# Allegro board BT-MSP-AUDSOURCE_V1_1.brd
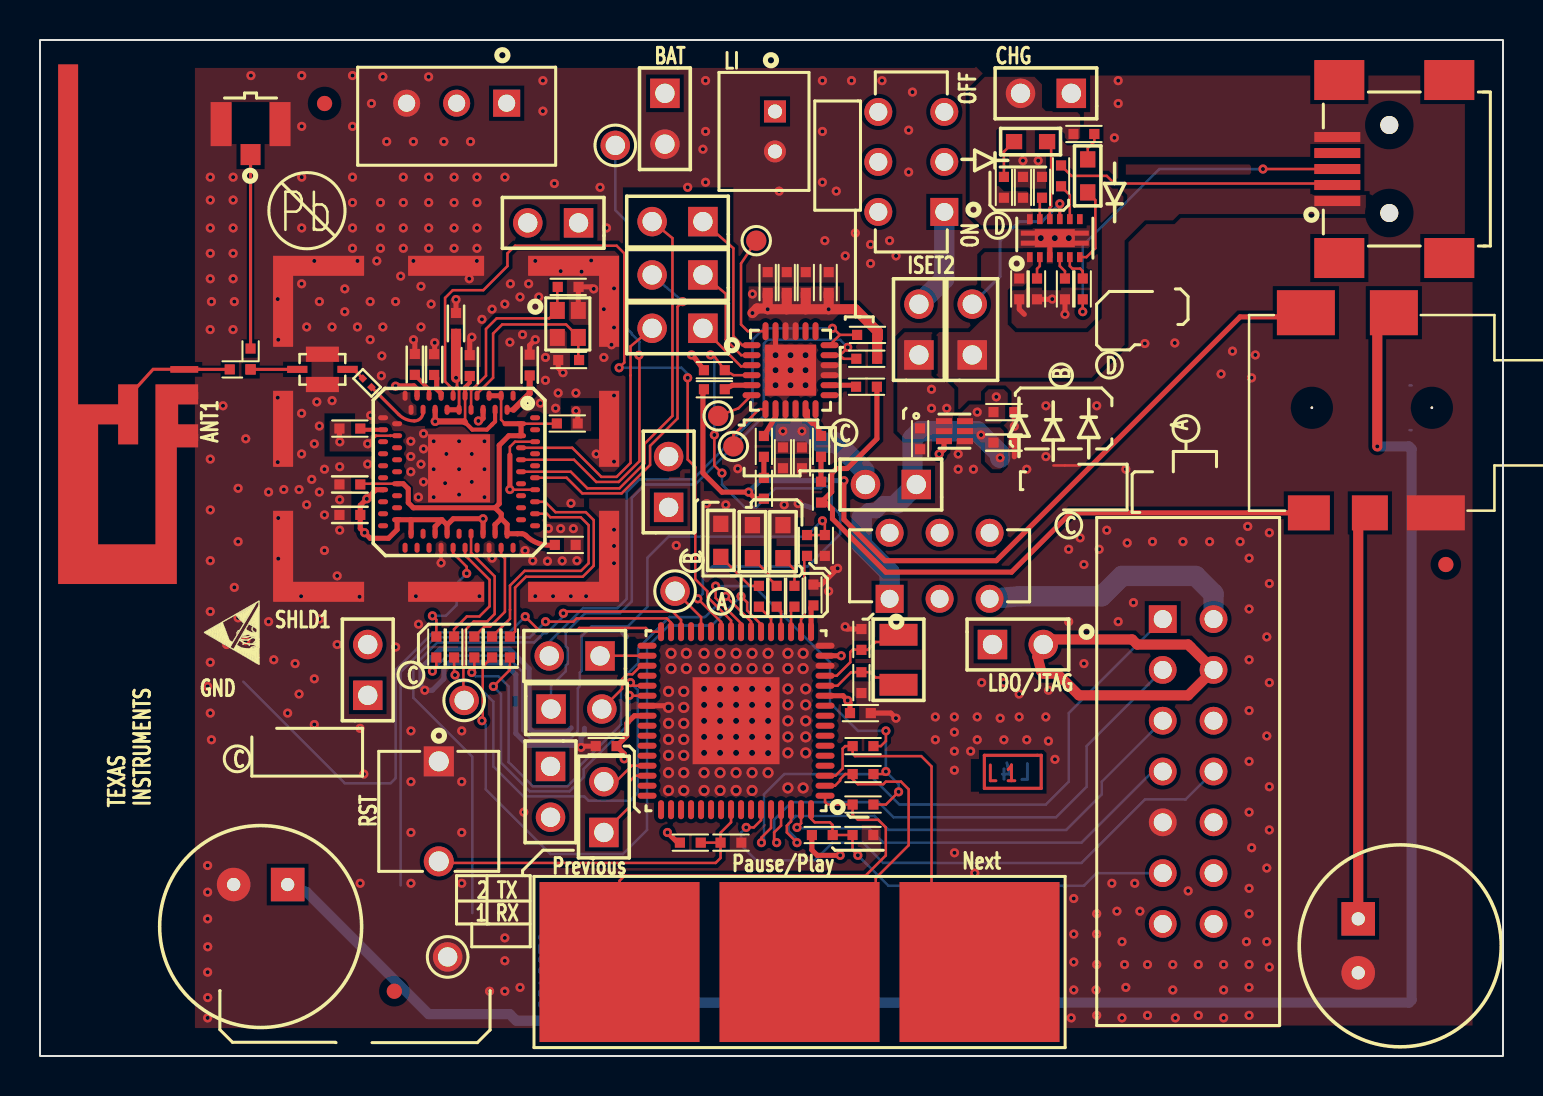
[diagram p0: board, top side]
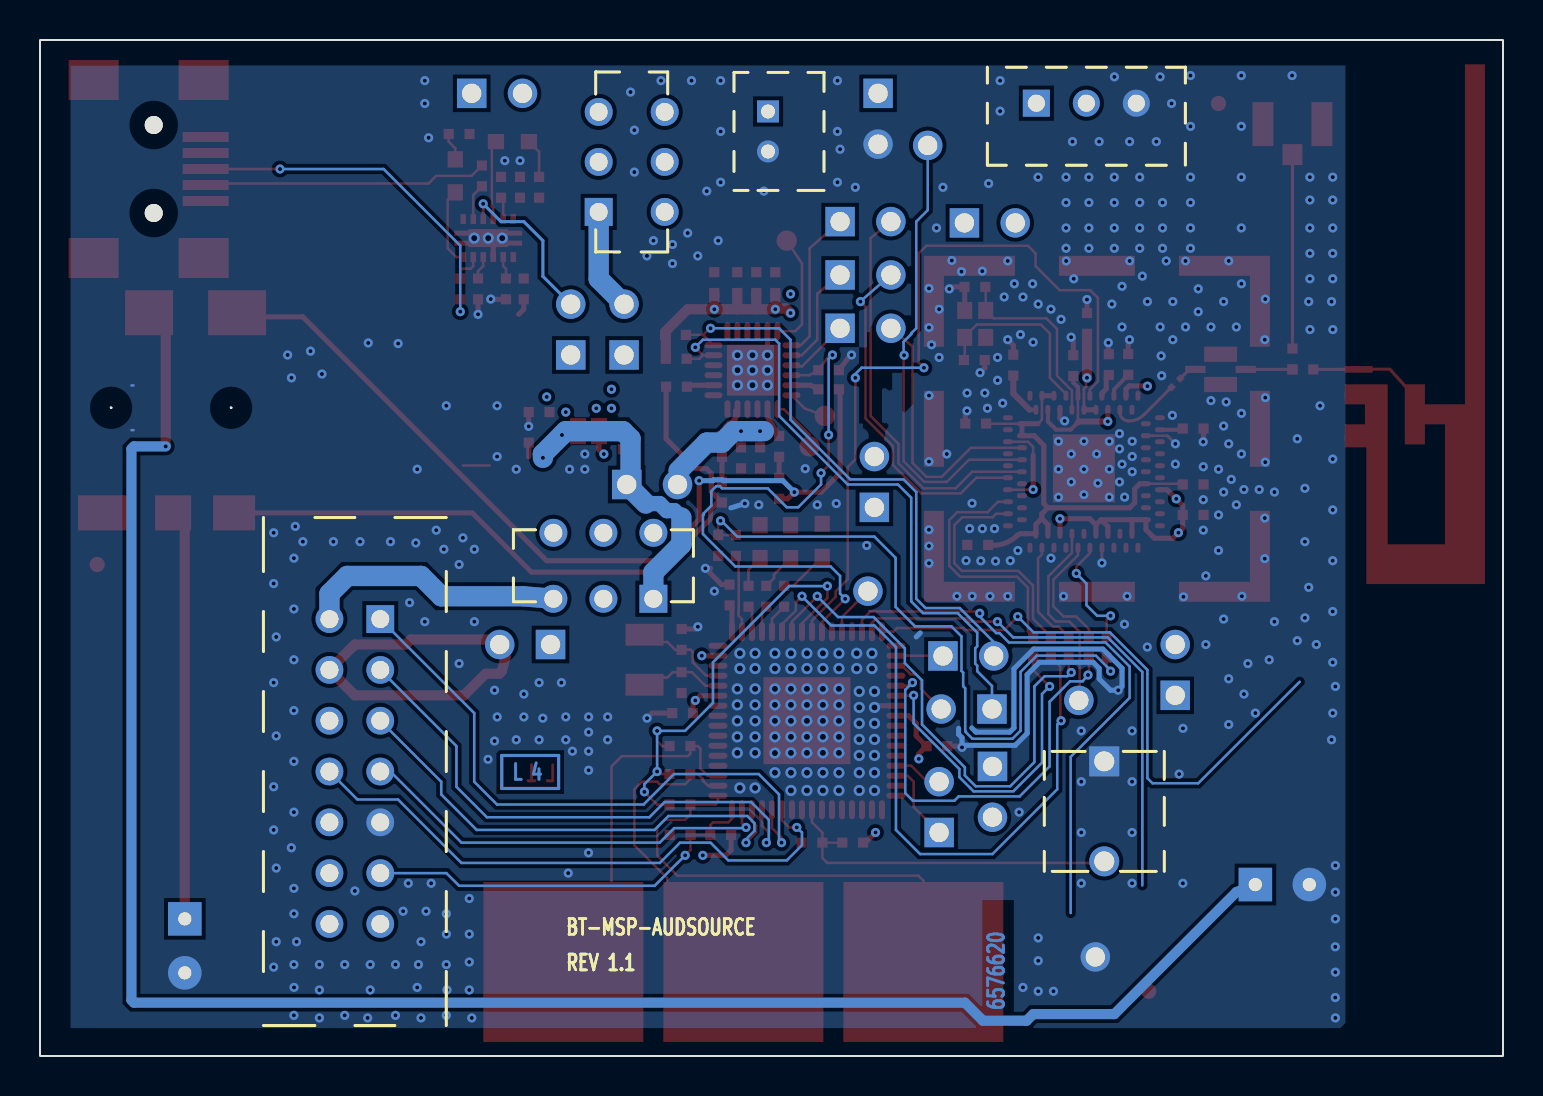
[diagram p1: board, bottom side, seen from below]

Outline 73.15 x 50.8 mm; copper layers: TOP, LYR2_GND, LYR3_PWR, BOTTOM. Coordinates in mm from the lower left corner of the outline.
Outline path: rectangle 0,0 73.15,50.8

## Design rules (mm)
net group PWR: nets DIG_LDO_OUT JTAG_PWR_3V3 VBAT_CC VCORE
nets with their own width: min track width 0.076; nets MLDO_OUT

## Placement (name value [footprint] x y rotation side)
ANT1  2.4-2.5 GHz  [ANT_IIFA_CC2420_32MIL_MIR_1]  7.21 37.73 90 top
C17  0.1uF  [0402]  15.49 27.05 180 top
C20  1.0uF  [0402]  21.49 34.52 90 top
C21  1.0uF  [0402]  20.8 36.63 90 top
C22  12pF  [0402]  26.41 38.46 180 top
C23  12pF  [0402]  26.43 34.8 0 top
C24  1.0uF  [0402]  48.2 30.67 0 top
C25  0.47uF  [0402]  15.49 28.58 180 top
C26  0.47uF  [0402]  26.26 25.56 0 top
C27  0.1uF  [0402]  15.49 31.37 180 top
C28  0.1uF  [0402]  19.71 34.57 90 top
C29  0.1uF  [0402]  18.74 34.58 90 top
C30  0.1uF  [0402]  24.48 34.55 90 top
C31  22pF  [0201]  16.36 33.66 135 top
C32  1.0uF  [0402]  48.96 38.35 270 top
C33  1.0uF  [0402]  48.2 32.19 0 top
C35  0.1uF  [0402]  26.36 31.63 0 top
C36  1.0uF  [0402]  49.15 43.43 90 top
C37  10uF  [0402]  28.31 15.49 180 top
C39  1.0uF  [0402]  41.02 17.14 0 top
C41  470nF  [0402]  38.67 23.05 90 top
C43  2.2nF  [0402]  41.15 11.05 0 top
C44  2.2nF  [0402]  34.55 10.67 0 top
C45  1.0uF  [0402]  44.01 30.86 270 top
C46  12pF  [0402]  41.07 20.83 270 top
C47  12pF  [0402]  41.07 18.67 90 top
C51  0.1uF  [0402]  38.1 29.91 90 top
C52  1.0uF  [0402]  37.15 29.91 90 top
C53  0.1uF  [0402]  37.34 38.67 90 top
C54  1.0uF  [0402]  36.39 38.67 90 top
C55  0.1uF  [0402]  38.29 38.67 90 top
C56  1.0uF  [0402]  39.43 38.67 90 top
C60  0.47uF  [0402]  39.05 30.48 90 top
C61  0.47uF  [0402]  36.2 30.48 90 top
D1  ORN  [LED_0603]  49.53 45.72 0 top
D2  YLW  [LED_0603]  37.15 25.72 90 top
D3  RED  [LED_0603]  35.62 25.72 90 top
D4  GRN  [LED_0603]  52.39 44.01 270 top
D5  GRN  [LED_0603]  34.04 25.78 90 top
FL1  2.45GHz  [FIL_4_85X53X41]  14.12 34.33 180 top
J2  MSP430 JTAG  [TE_5103308-2]  56.14 21.84 270 top
J3  LI-POL BAT HEADER  [JST_B2B-PH-K-S]  36.75 47.23 270 top
J4  USB Port  [JAE_DX2R005HN2]  69.32 44.35 90 top
J5  1x2 THVT  [HDR_THVT_1X2_100_M]  25.53 14.48 0 top
J6  1x2 THVT  [HDR_THVT_1X2_100_M]  47.62 20.57 90 top
J11  1x2 THVT  [HDR_THVT_1X2_100_M]  26.93 41.66 270 top
J12  1x2 THVT  [HDR_THVT_1X2_100_M]  16.39 18.03 180 top
J13  1x2 THVT  [HDR_THVT_1X2_100_M]  51.57 48.13 270 top
J14  1x2 THVT  [HDR_THVT_1X2_100_M]  46.61 35.05 180 top
J15  1x2 THVT  [HDR_THVT_1X2_100_M]  28.19 11.18 180 top
J16  1x2 THVT  [HDR_THVT_1X2_100_M]  43.95 35.05 180 top
J17  HEADER 1  [TP101H50]  31.76 23.24 270 top
J18  HEADER 1  [TP101H50]  21.21 17.78 0 top
J22  1x2 THVT  [HDR_THVT_1X2_100_M]  31.25 48.13 0 top
J23  HEADER 1  [TP101H50]  28.77 45.53 0 top
J26  AA BAT HEADER  [MOLEX_22-03-5035]  23.33 47.64 180 top
J28  MIC1  [MIC_THVT_CMA-4544PF-W]  12.38 8.57 180 top
J29  HEADER 1  [TP101H50]  20.38 4.95 0 top
J30  1x2 THVT  [HDR_THVT_1X2_100_M]  43.81 28.57 270 top
J31  1x2 THVT  [HDR_THVT_1X2_100_M]  31.43 27.43 180 top
J32  1x2 THVT  [HDR_THVT_1X2_100_M]  33.15 41.72 270 top
J33  1x2 THVT  [HDR_THVT_1X2_100_M]  33.15 39.05 270 top
J34  1x2 THVT  [HDR_THVT_1X2_100_M]  25.55 17.35 90 top
J35  1x2 THVT  [HDR_THVT_1X2_100_M]  33.15 36.39 270 top
J36  1x2 THVT  [HDR_THVT_1X2_100_M]  28 20 270 top
J37  MIC2  [MIC_THVT_CMA-4544PF-W]  65.91 6.86 270 top
J39  PHONOJACK STEREO-15  [JACK_SM_SJ1_3515]  69.6 32.41 180 top
NOREF  -  []  5.96 81.94 90 top
NOREF#2  -  [unnamed#2]  14.23 47.62 0 top
NOREF#3  -  [unnamed#2]  70.29 24.57 0 top
NOREF#4  -  []  363.1 -64.01 0 top
NOREF#5  -  []  25.53 15.62 90 top
NOREF#6  -  []  24.52 16.64 180 top
NOREF#7  -  []  18.55 38.86 180 top
NOREF#8  -  []  25.53 38.86 180 top
NOREF#9  -  []  13.09 16.64 90 top
NOREF#10  -  []  18.55 38.86 180 top
NOREF#11  -  []  25.53 15.62 180 top
NOREF#12  -  [unnamed#2]  17.72 3.24 0 top
NOREF#13  -  []  17.28 38.86 180 top
NOREF#14  -  []  38.74 61.01 180 bottom
P3  COAXIAL  [HRS_U-FL-R-SMT-1]  10.53 46.6 0 top
R3  2.7K  [0402]  49.85 38.35 270 top
R4  1.5K  [0402]  48.2 43.43 90 top
R5  2.0K  [0402]  51.25 38.35 270 top
R6  470R  [0402]  37.72 22.99 90 top
R7  470R  [0402]  36.84 22.99 90 top
R8  10K  [0402]  50.1 43.43 90 top
R9  1.5K  [0402]  52.2 46.1 0 top
R10  10K  [0402]  38.35 25.53 90 top
R11  18K  [0402]  39.24 25.53 270 top
R12  47K  [0402]  32.52 10.67 0 top
R13  0R  [0402]  51.05 44.01 270 top
R14  0R  [0402]  52.14 38.35 90 top
R15  470R  [0402]  35.95 22.99 90 top
R16  2.7K  [0402]  41.34 34.86 180 top
R17  2.7K  [0402]  41.38 36.06 180 top
R19  2.2K  [0402]  33.72 33.34 0 top
R20  2.2K  [0402]  41.33 33.46 0 top
R25  0R  [0402]  19.82 20.45 270 top
R26  0R  [0402]  23.5 20.45 270 top
R27  0R  [0402]  20.71 20.45 270 top
R28  47K  [0402]  39.12 11.05 0 top
R29  0R  [0402]  10.01 34.33 0 top
R30  0R  [0402]  10.53 34.85 270 top
R31  75k  [0402]  41.15 12.57 180 top
R32  75k  [0402]  41.15 14.1 180 top
R33  75k  [0402]  41.15 15.49 180 top
R34  0R  [0402]  22.61 20.45 270 top
R35  0R  [0402]  21.72 20.45 270 top
R36  0R  [0402]  36.2 28.38 270 top
R37  0R  [0402]  39.05 28.19 270 top
R39  10K  [0402]  33.72 34.29 180 top
S1  BUTTON  [SW_EVQ-11A05R]  19.94 14.73 270 top
S2  POS 2 SW  [SW_JS202011CQN]  45.22 42.2 180 top
S3  POS 2 SW  [SW_JS202011CQN]  42.48 22.86 90 top
SHLD1  RF SHIELD COVER  [SH_BMI-S-202_650X650]  28.96 22.71 90 top
TP7  XX  [TP102]  35.81 40.77 0 top
TP8  XX  [TP102]  34.67 30.48 0 top
TP11  XX  [TP102]  33.91 32 0 top
U5  CC2560RVM  [PVQFN_RVM_EP134X122]  20.95 29.21 180 top
U8  TLV7101828DSER  [SON50P150X150X80-6]  45.73 31.24 270 top
U9  BQ24055DSST  [SON50P300X200X80-13]  50.74 40.89 90 top
U10  MSP430F5229IRGCR  [QFN50P900X900X100-65NA]  34.8 16.76 180 top
U11  Electrodes  [3PELECTRODE]  37.98 4.7 0 top
U12  TLV320ADC3101  [QFN50P400X400X100-25N]  37.53 34.29 0 top
Y1  26MHz  [XTAL200X160X50]  26.39 36.6 0 top
Y2  32.768KHz  [XTAL_2_SM_130X63]  42.93 19.81 90 top

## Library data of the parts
ANT1 = ANT_IIFA_CC2420_32mil_MIR
C17 C20-C30 C32 C33 C35-C37 C39 C41 C43-C47 C51-C56 C60 C61 = CAP_NP: alternate symbols: (0402_SMALL)
C31 = CAP_NP: alternate symbols: (0201_small)
D1-D5 = LED_2P
FL1 = FILTER_4PIN_GND
J2 = CONN PCB 7x2
J3 = BATTERY
J4 = USB Port_3
J5 J6 J11-J16 J22 J30-J36 = Header_1x2
J17 J18 J23 J29 = HEADER 1
J26 = AA BAT HEADER
J28 J37 = MIC_0
J39 = PHONOJACK STEREO-15
P3 = CON_COAXIAL_UFL-R-SMT_0
R3-R17 R19 R20 R25-R37 R39 = RESISTOR: alternate symbols: (0402_SMALL)
S1 = BUTTON
S2 = BUTTON_3
S3 = Switch_0
SHLD1 = RF_SHIELD_8P
TP7 TP8 TP11 = TESTPOINT
U5 = BL6450Q_RVM
U8 = TLV7101828_0
U9 = bq24055_1
U10 = MSP430F5229IRGC_1
U11 = Electrodes
U12 = TLV320ADC3101_0
Y1 = XTAL_4P_GND
Y2 = 32_12.768KHz

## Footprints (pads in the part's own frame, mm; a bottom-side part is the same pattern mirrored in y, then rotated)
3PELECTRODE
  rect 8x8 smd: 1(-9,0) 2(0,0) 3(9,0)
0201
  rect 0.305x0.305 smd: 1(-0.305,0) 2(0.305,0)
0402
  rect 0.508x0.508 smd: 1(-0.521,0) 2(0.521,0)
ANT_IIFA_CC2420_32MIL_MIR_1
  rect 0.33x1.397 smd: 1(-3.404,0) 2(-4.699,0) 3(-6.807,0)
FIL_4_85X53X41
  rect 1.651x0.762 smd: 1(0,0.757) 3(0,-0.757)
  rect 1.016x0.356 smd: 2(1.257,0) 4(-1.257,0)
HDR_THVT_1X2_100_M
  rect 1.473x1.473 hole 0.965: 1(0,0)
  round 1.473 hole 0.965: 2(0,-2.54)
HRS_U-FL-R-SMT-1
  rect 1x1.05 smd: 1(0,-1.525)
  rect 1.05x2.2 smd: 2A(-1.475,0) 2B(1.475,0)
JACK_SM_SJ1_3515
  round 0.127 hole 1.6 unplated: (0,0) (6,0)
  rect 2.9x1.75 smd: 1(-0.2,5.254)
  rect 2.9x2.25 smd: 2(6.3,-4.754)
  rect 2.1x1.75 smd: 3(6.15,5.254)
  rect 2.4x2.25 smd: 4(1.9,-4.754)
  rect 1.8x1.75 smd: 5(3.1,5.254)
JAE_DX2R005HN2
  round 0.9 hole 0.899 unplated: (-2.2,1.85) (2.2,1.85)
  rect 0.5x2.3 smd: 1(-1.6,4.45) 2(-0.8,4.45) 3(0,4.45) 4(0.8,4.45) 5(1.6,4.45)
  rect 2x2.5 smd: G1(-4.45,4.35) G2(4.45,4.35) G3(-4.45,-1.15) G4(4.45,-1.15)
JST_B2B-PH-K-S
  rect 1.1x1.1 hole 0.7: 1(0,0)
  round 1.1 hole 0.7: 2(2,0)
LED_0603
  rect 0.813x0.762 smd: 1(-0.826,0) 2(0.826,0)
MIC_THVT_CMA-4544PF-W
  rect 1.676x1.676 hole 0.66: 1(0,0)
  round 1.676 hole 0.66: 2(2.7,0)
MOLEX_22-03-5035
  rect 1.354x1.354 hole 0.854: 1(0,0)
  round 1.354 hole 0.854: 2(2.5,0) 3(5,0)
PVQFN_RVM_EP134X122
  oval 0.25x0.5 smd: A1(-2.7,-3.8) A2(-2.101,-3.8) A3(-1.501,-3.8) A4(-0.899,-3.8) A5(-0.3,-3.8) A6(0.3,-3.8) A7(0.899,-3.8) A8(1.501,-3.8) A9(2.101,-3.8) A10(2.7,-3.8) A21(2.7,3.8) A22(2.101,3.8) A23(1.501,3.8) A24(0.899,3.8) A25(0.3,3.8) A26(-0.3,3.8) A27(-0.899,3.8) A28(-1.501,3.8) A29(-2.101,3.8) A30(-2.7,3.8) B1(-2.4,-3.099) B2(-1.801,-3.099) B3(-1.199,-3.099) B4(-0.599,-3.099) B5(0,-3.099) B6(0.599,-3.099) B7(1.199,-3.099) B8(1.801,-3.099) B9(2.4,-3.099) B19(2.4,3.099) B20(1.801,3.099) B21(1.199,3.099) B22(0.599,3.099) B23(0,3.099) B24(-0.599,3.099) B25(-1.199,3.099) B26(-1.801,3.099) B27(-2.4,3.099)
  oval 0.5x0.25 smd: A11(3.8,-2.7) A12(3.8,-2.101) A13(3.8,-1.501) A14(3.8,-0.899) A15(3.8,-0.3) A16(3.8,0.3) A17(3.8,0.899) A18(3.8,1.501) A19(3.8,2.101) A20(3.8,2.7) A31(-3.8,2.7) A32(-3.8,2.101) A33(-3.8,1.501) A34(-3.8,0.899) A35(-3.8,0.3) A36(-3.8,-0.3) A37(-3.8,-0.899) A38(-3.8,-1.501) A39(-3.8,-2.101) A40(-3.8,-2.7) B10(3.099,-2.4) B11(3.099,-1.801) B12(3.099,-1.199) B13(3.099,-0.599) B14(3.099,0) B15(3.099,0.599) B16(3.099,1.199) B17(3.099,1.801) B18(3.099,2.4) B28(-3.099,2.4) B29(-3.099,1.801) B30(-3.099,1.199) B31(-3.099,0.599) B32(-3.099,0) B33(-3.099,-0.599) B34(-3.099,-1.199) B35(-3.099,-1.801) B36(-3.099,-2.4)
  rect 3.099x3.404 smd: EPAD(0,-0.17)
QFN50P400X400X100-25N
  oval 0.9x0.3 smd: 1(-1.95,1.25) 2(-1.95,0.75) 3(-1.95,0.25) 4(-1.95,-0.25) 5(-1.95,-0.75) 6(-1.95,-1.25) 13(1.95,-1.25) 14(1.95,-0.75) 15(1.95,-0.25) 16(1.95,0.25) 17(1.95,0.75) 18(1.95,1.25)
  oval 0.3x0.9 smd: 7(-1.25,-1.95) 8(-0.75,-1.95) 9(-0.25,-1.95) 10(0.25,-1.95) 11(0.75,-1.95) 12(1.25,-1.95) 19(1.25,1.95) 20(0.75,1.95) 21(0.25,1.95) 22(-0.25,1.95) 23(-0.75,1.95) 24(-1.25,1.95)
  rect 2.55x2.55 smd: 25(0,0)
QFN50P900X900X100-65NA
  oval 0.95x0.3 smd: 1(-4.45,3.75) 2(-4.45,3.25) 3(-4.45,2.75) 4(-4.45,2.25) 5(-4.45,1.75) 6(-4.45,1.25) 7(-4.45,0.75) 8(-4.45,0.25) 9(-4.45,-0.25) 10(-4.45,-0.75) 11(-4.45,-1.25) 12(-4.45,-1.75) 13(-4.45,-2.25) 14(-4.45,-2.75) 15(-4.45,-3.25) 16(-4.45,-3.75) 33(4.45,-3.75) 34(4.45,-3.25) 35(4.45,-2.75) 36(4.45,-2.25) 37(4.45,-1.75) 38(4.45,-1.25) 39(4.45,-0.75) 40(4.45,-0.25) 41(4.45,0.25) 42(4.45,0.75) 43(4.45,1.25) 44(4.45,1.75) 45(4.45,2.25) 46(4.45,2.75) 47(4.45,3.25) 48(4.45,3.75)
  oval 0.3x0.95 smd: 17(-3.75,-4.45) 18(-3.25,-4.45) 19(-2.75,-4.45) 20(-2.25,-4.45) 21(-1.75,-4.45) 22(-1.25,-4.45) 23(-0.75,-4.45) 24(-0.25,-4.45) 25(0.25,-4.45) 26(0.75,-4.45) 27(1.25,-4.45) 28(1.75,-4.45) 29(2.25,-4.45) 30(2.75,-4.45) 31(3.25,-4.45) 32(3.75,-4.45) 49(3.75,4.45) 50(3.25,4.45) 51(2.75,4.45) 52(2.25,4.45) 53(1.75,4.45) 54(1.25,4.45) 55(0.75,4.45) 56(0.25,4.45) 57(-0.25,4.45) 58(-0.75,4.45) 59(-1.25,4.45) 60(-1.75,4.45) 61(-2.25,4.45) 62(-2.75,4.45) 63(-3.25,4.45) 64(-3.75,4.45)
  rect 4.35x4.35 smd: 65(0,0)
SH_BMI-S-202_650X650
  rect 0.356x0.356 smd: 1(0.5,0.5) 2(8.65,0.5) 3(16.75,0.5) 4(16.8,8.65) 5(16.75,16.75) 6(8.65,16.8) 7(0.5,16.75) 8(0.5,8.65)
SON50P150X150X80-6
  rect 0.3x0.8 smd: 1(-0.5,-0.525) 2(0,-0.525) 3(0.5,-0.525) 4(0.5,0.525) 5(0,0.525) 6(-0.5,0.525)
SON50P300X200X80-13
  rect 0.5x0.28 smd: 1(-0.95,1.25) 2(-0.95,0.75) 3(-0.95,0.25) 4(-0.95,-0.25) 5(-0.95,-0.75) 6(-0.95,-1.25) 7(0.95,-1.25) 8(0.95,-0.75) 9(0.95,-0.25) 10(0.95,0.25) 11(0.95,0.75) 12(0.95,1.25)
  custom 0.225x0.225 smd: 13(0,0)
SW_EVQ-11A05R
  rect 1.5x1.5 hole 1: 1(0,0)
  round 1.5 hole 1: 2(5,0)
SW_JS202011CQN
  rect 1.4x1.4 hole 0.899: 1(0,0)
  round 1.4 hole 0.899: 2(0,-2.5) 3(0,-5) 4(3.3,0) 5(3.3,-2.5) 6(3.3,-5)
TE_5103308-2
  rect 1.39x1.39 hole 0.899: 1(0,0)
  round 1.39 hole 0.899: 2(0,2.54) 3(2.54,0) 4(2.54,2.54) 5(5.08,0) 6(5.08,2.54) 7(7.62,0) 8(7.62,2.54) 9(10.16,0) 10(10.16,2.54) 11(12.7,0) 12(12.7,2.54) 13(15.24,0) 14(15.24,2.54)
TP101H50
  round 1.473 hole 0.965: 1(0,0)
TP102
  round 1.016 smd: 1(0,0)
unnamed#2
  round 0.762 smd: (0,0)
XTAL200X160X50
  rect 0.75x0.85 smd: 1(-0.525,0.675) 2(-0.525,-0.675) 3(0.525,-0.675) 4(0.525,0.675)
XTAL_2_SM_130X63
  rect 1.092x1.905 smd: 1(-1.25,0) 2(1.25,0)

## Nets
AVDD_MIC: C51.2 C52.2 J30.2 U12.10(AVDD)
GND: ANT1.2(G2) ANT1.3(G1) C17.2 C20.2 C21.2 C22.1 C23.1 C24.2 C25.2 C26.2 C27.2 C28.2 C29.2 C30.2 C32.2 C33.2 C35.2 C36.2 C37.2 C39.2 C41.2 C43.2 C44.2 C45.2 C46.1 C47.1 C51.1 C52.1 C53.2 C54.2 C55.2 C56.2 D2.2(CATHODE) D3.2(CATHODE) D5.2(CATHODE) FL1.1(GND#1) FL1.3(GND#3) J2.9(12) J3.2(GND) J4.5(GND) J22.2 J26.3(-) J28.2 J29.1 J37.2 J39.1 P3.2A(GND#2A) P3.2B(GND#2B) R3.2 R5.2 R8.2 R11.2 R39.2 S1.1 SHLD1.1(G1) SHLD1.2(G2) SHLD1.3(G3) SHLD1.4(G4) SHLD1.5(G5) SHLD1.6(G6) SHLD1.7(G7) SHLD1.8(G8) U5.A10(NC_2) U5.A11(NC_3) U5.A24(VSS_1) U5.A28(VSS_2) U5.B3(VSS_FREF) U5.B9(NC_14) U5.B10(NC_15) U5.B11(VSS_DCO) U5.EPAD(VSS_3) U8.4(GND) U9.3(VSS) U9.13 U10.14(AVSS) U10.16(DVSS) U10.39(DVSS_2) U10.65(DVSS_3) U12.9(AVSS) U12.15(I2C_ADR0) U12.16(I2C_ADR1) U12.23(DVSS) U12.25(EPAD) Y1.2(GND#2) Y1.4(GND#4)
VBAT: C45.1 J11.1 J16.1 U8.1(EN1) U8.2(IN)
VBAT_CC: C21.1 J11.2 U5.B5(MLDO_IN) U5.B6(CL1.5_LDO_IN)
VCC_5229: C39.1 J6.1 R28.1 S3.2 U10.11(AVCC) U10.15(DVCC)
VDD_1V8_LDO: C33.1 J5.1 J12.1 J31.1 U8.3(EN2) U8.6(OUT1)
VDD_2V8_LDO: C24.1 J30.1 S3.1 U8.5(OUT2)
ALO: C29.1 U5.A8(ADCPPA_LDO_OUT)
ANT: ANT1.1(FEED) R29.1
AUD_CLK_1V8_CC: J32.2 U5.B32(AUD_CLK)
AUD_FSYNC_1V8_CC: J33.2 U5.A35(AUD_FSYNC)
AUD_IN_1V8_CC: J35.2 U5.B34(AUD_IN)
AUDIO_NRESET_1V8_5229: R39.1 U10.26(P2.0) U12.4(NRESET)
BT_RF: C31.1 U5.B8(BT_RF)
BT_RF_IN: C31.2 FL1.4(IN)
CB0: R31.2 U10.1(P6.0/CB0) U11.1(PAD1)
CB1: R32.2 U10.2(P6.1/CB1) U11.2(PAD2)
CB2: R33.2 U10.3(P6.2/CB2) U11.3(PAD3)
CBOUT: R31.1 R32.1 R33.1 U10.24(P1.6)
CLO: C28.1 U5.A7(CL1.5_LDO_OUT)
DCLO: C27.1 U5.A12(DCO_LDO_OUT)
DIG_LDO_OUT: C25.1 C26.1 C35.1 U5.A2(DIG_LDO_OUT_1) U5.A3(DIG_LDO_OUT_2) U5.B15(DIG_LDO_OUT_3) U5.B26(DIG_LDO_OUT_4) U5.B27(DIG_LDO_OUT_5) U5.B35(DIG_LDO_OUT_6) U5.B36(DIG_LDO_OUT_7)
DVIO_1V8_5229: C37.1 J5.2 R12.1 U10.40(DVIO)
HCI_CTS_1V8_CC: R35.2 U10.23(P1.5)
HCI_RTS_1V8_CC: R34.2 U10.22(P1.4)
HCI_RX_1V8_CC: R27.2 U10.37(P3.3/UCA0TXD)
HCI_TX_1V8_CC: R26.2 U10.38(P3.4/UCA0RXD)
I2C_SCL_1V8_5229: J34.2 U10.35(P3.1/UCB0SCL)
I2C_SDA_1V8_5229: J36.1 U10.34(P3.0/UCB0SDA)
IOVDD_1V8_MIC: C53.1 C54.1 C55.1 C56.1 J31.2 R16.1 R17.1 U12.21(IOVDD) U12.22(DVDD)
JTAG_PWR_3V3: J2.2(1) S3.3
LED1: R6.1 U10.19(P1.1)
LED2: R7.1 U10.20(P1.2)
LED3: R15.1 U10.21(P1.3)
MLDO_OUT: C20.1 U5.A5(MLDO_OUT_1) U5.A9(MLDO_OUT_2) U5.B2(MLDO_OUT_3) U5.B7(MLDO_OUT_4)
NRST/SBWTDIO_5229: C43.1 J2.11(13) R28.2 U10.64(NRSTDVCC/SBWTDIO)
NSHUTDOWN_1V8_CC: U5.A6(NSHUTD) U10.25(P1.7)
RF_ANT: FL1.2(OUT) R29.2 R30.2
SLO: C30.1 U5.B1(SRAM_LDO_OUT)
SLOW_CLK_1V8_CC: R10.2 R11.1 R25.2
SMCLK_5229: J17.1 U10.28(P2.2)
TCK_5229: J2.7(11) U10.63(PJ.3/TCK)
TDI_5229: J2.3(9) U10.61(PJ.1/TDI)
TDO_5229: J2.1(8) U10.60(PJ.0/TDO)
TEST/SBWTCK_5229: J2.8(4) U10.59(TEST/SBWTCK)
TMS_5229: J2.5(10) U10.62(PJ.2/TMS)
UBAL5: P3.1 R30.1
USB_5V: C32.1 J4.1(VBUS) J14.1 U9.1(IN)
VCORE: C41.1 U10.17(VCORE)
VIO_1V8_CC: C17.1 J12.2 U5.A17(VDD_IO_1) U5.A34(VDD_IO_2) U5.A38(VDD_IO_3) U5.B18(VDD_IO_4) U5.B19(VDD_IO_5) U5.B21(VDD_IO_6) U5.B22(VDD_IO_7) U5.B25(VDD_IO_8)
N81643: U10.31(P2.5)
N81789: U10.30(P2.4)
N134906: J36.2 R17.2 U12.18(SDA)
N140210: J37.1 J39.5
N140367: C60.1 R37.1
N148311: J32.1 U12.1(BCLK)
N148461: J35.1 U12.3(DOUT)
N148590: J33.1 U12.2(WCLK)
N151083: C60.2 U12.11(IN1R)
N151287: J28.1 J39.4
N151328: R19.2 U12.5(MICBIAS1)
N151337: C61.2 U12.8(IN1L)
N153645: J34.1 R16.2 U12.17(SCL)
N160490: J4.2(D-) R13.1
N163005: R20.1 U12.14(MICBIAS2)
N180634: J39.2 R19.1 R36.2
N180654: C61.1 R36.1
N180794: J39.3 R20.2 R37.2
N200636: R3.1 U9.2(ISET)
N200648: C36.1 J13.2 R4.1 R9.1 U9.12(OUT)
N200654: D1.2(CATHODE) U9.10(NCHG)
N200660: D1.1(ANODE) R4.2
N200680: R5.1 U9.4(PRETERM)
N200686: J14.2 U9.9(ISET2)
N200702: J3.1(POS) J13.1 J22.1 J26.1(+) S2.2
N200706: R14.2 U9.5(D+)
N200710: R13.2 U9.8(D-)
N200714: D4.2(CATHODE) U9.6(NPG)
N200730: R8.1 U9.11(TS)
N200762: J4.3(D+) R14.1
N200794: J16.2 S2.1
N201837: R34.1 U5.A32(HCI_RTS)
N201839: R35.1 U5.A29(HCI_CTS)
N201841: R26.1 U5.A33(HCI_TX)
N201843: R27.1 U5.A26(HCI_RX)
N202027: C22.2 U5.B4(FREFP) Y1.1
N202029: C23.2 U5.A4(FREFM) Y1.3
N202071: R25.1 U5.A25(SLOW_CLK_IN)
N202119: J18.1 U5.B24(TX_DBG)
N203803: C46.2 U10.13(P5.5/XOUT) Y2.2(OUT)
N203825: C47.2 U10.12(P5.4/XIN) Y2.1(IN)
N203855: J15.1 U10.46(P4.5/PM_UCA1RXD)
N203891: C44.1 R12.2 S1.2 U10.56(NRST/NMI)
N203905: D2.1(ANODE) R6.2
N203911: D3.1(ANODE) R7.2
N203925: R10.1 U10.18(P1.0)
N203941: J2.4(2) J6.2
N203951: J15.2 U10.45(P4.4/PM_UCA1TXD)
N203983: U10.32(P2.6)
N203997: D5.1(ANODE) R15.2
N205896: J23.1 U5.B33(AUD_OUT)
N1641850: TP8.1 U12.7(IN2L)
N1644250: TP11.1 U12.6(IN3L)
N1647250: TP7.1 U12.24(MCLK)
N2008820: D4.1(ANODE) R9.2

Pads without a net: J2 6 10 12 13 14; J4 4 G1 G2 G3 G4; J26 2; S2 3 4 5 6; S3 4 5 6; U5 A1 A13 A14 A15 A16 A18 A19 A20 A21 A22 A23 A27 A30 A31 A36 A37 A39 A40 B12 B13 B14 B16 B17 B20 B23 B28 B29 B30 B31; U9 7; U10 4 5 6 7 8 9 10 27 29 33 36 41 42 43 44 47 48 49 50 51 52 53 54 55 57 58; U12 12 13 19 20

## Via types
v1: diameter 0.457, hole 0.203, TOP to BOTTOM, 452 vias
v2: diameter 0.559, hole 0.305, TOP to BOTTOM, 90 vias

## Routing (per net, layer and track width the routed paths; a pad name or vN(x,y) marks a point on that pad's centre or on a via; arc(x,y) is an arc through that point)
AVDD_MIC: length 5.8
  BOTTOM w0.127: J30.2 41.22,29.26
  BOTTOM w1.016: 41.22,29.26 39.81,30.67 39.05,30.67 38.48,31.24 v1(38.1,31.24) v1(37.15,31.24) 36.96,31.24
GND: length 52.3
  TOP w0.127: 17.53,31.01 16.79,31.01 ; 52.01,29.53 50.67,29.53 ; U5.B11 17.53,31.01
  TOP w0.152: 16.79,31.01 v1(16.38,30.61) ; 17.53,31.01 17.53,31.01 ; U5.A24 v1(20.06,24.65)
  TOP w0.254: v1(40.26,21.46) 40.37,21.35 C46.1 ; C32.2 48.96,37.34 49.22,37.08 ; C21.2 v1(20.8,37.82) ; 39.62,24.38 v1(39.88,24.38) 39.07,23.57 C41.2 ; U5.B3 22.15,32.31 22.15,31.89 22.02,31.75 v1(21.92,31.75) ; R39.2 32.63,35.05 v1(32.58,35.05) ; v1(51.25,37.08) R5.2 ; C29.2 18.74,35.75 v1(18.67,35.81) ; v2(31.43,17.43) 31.34,17.51 U10.39 ; v1(50.61,37.85) 50.6,37.83 R3.2 ; U12.23 v2(36.78,35.04) ; C39.2 42.55,17.14 v1(42.8,16.89) ; C27.2 14.97,30.73 v1(14.99,30.71) ; C28.2 19.74,35.12 v1(19.74,35.66) ; v1(21.6,35.94) 21.49,35.83 C20.2 ; v1(26.15,34.17) 25.91,34.4 C23.1 ; v1(26.8,32.26) 26.89,32.17 C35.2 ; C24.2 48.72,29.96 ; v2(50.74,40.89) 50.49,40.64 U9.3 ; v1(27.69,38.35) 27.58,38.46 C22.1 26.92,38.44 Y1.4 ; C33.2 v1(48.72,31.48) ; C37.2 27.11,15.49 v1(27.05,15.43) ; v1(24.76,35.82) 24.48,35.54 C30.2
  BOTTOM w0.127: 68.58,33.53 68.48,33.53 ; 68.48,31.29 68.58,31.29
  BOTTOM w0.254: 27.22,16.38 27.22,16.09 27.05,15.92 v1(27.05,15.43) 26.95,15.53 24.39,15.53 23.79,16.13 23.79,19.07 23.18,19.68 20.49,19.68 20.19,19.39 20.19,18.86 19.62,18.29 v1(19.24,18.29) 19.05,18.48 19.05,19.39 20.01,20.35 23.47,20.35 24.45,19.36 24.45,16.4 24.66,16.19 26.33,16.19 26.36,16.22 26.37,16.22 26.56,16.4 ; 38.61,27.4 v1(37.91,27.62) ; 29.14,21.15 29.34,20.95
  vias: v1(8.38,18.48) v1(8.38,9.53) v1(8.38,8.19) v1(8.38,6.86) v1(8.39,5.46) v1(8.38,4.19) v1(8.39,2.92) v1(8.38,1.91) v1(8.51,43.94) v1(8.51,42.8) v1(8.51,41.4) v1(8.51,40.13) v1(8.51,38.86) v1(8.51,36.32) v1(8.51,29.84) v1(8.51,27.3) v1(8.51,24.77) v1(8.51,22.23) v1(8.51,19.68) v1(8.51,17.14) v1(8.57,37.72) v1(8.57,15.81) v1(9.15,32.51) v1(9.33,20.57) v1(9.66,43.94) v1(9.66,42.8) v1(9.66,41.4) v1(9.66,40.13) v1(9.66,38.86) v1(9.72,37.72) v1(9.65,36.32) v1(9.72,23.43) v1(9.91,28.38) v1(9.91,25.72) v1(9.91,21.91) v1(10.29,30.86) v1(10.29,20.76) v1(10.55,49.02) v1(11.43,28.2) v1(11.43,21.72) v1(11.69,19.81) v1(11.89,37.85) v1(11.91,35.81) v1(11.89,32.92) v1(11.89,29.69) v1(11.91,26.9) v1(11.91,24.87) v1(12.19,28.32) v1(12.38,17.14) v1(12.76,19.62) v1(12.95,28.32) v1(12.95,18.1) v1(13.09,49.02) v1(13.09,46.48) v1(13.09,43.94) v1(13.09,41.4) v1(13.08,38.61) v1(13.08,32.13) v1(13.08,30.1) v1(13.06,22.99) v1(13.33,36.45) v1(13.33,27.56) v1(13.59,28.83) v1(13.72,39.75) v1(13.72,30.61) v1(13.72,18.86) v1(13.72,16.57) v1(13.84,32.71) v1(13.97,37.72) v1(13.97,31.5) v1(13.97,28.2) v1(13.97,21.85) v1(14.22,29.34) v1(14.22,27.05) v1(14.22,25.28) v1(14.6,36.45) v1(14.6,32.77) v1(14.86,24.01) v1(14.86,20.57) v1(14.99,29.46) v1(14.99,27.82) v1(14.99,26.29) v1(15.24,38.36) v1(15.24,37.21) v1(15.63,49.02) v1(15.63,46.48) v1(15.63,43.94) v1(15.63,42.67) v1(15.63,41.4) v1(15.63,40.39) v1(15.87,39.75) v1(15.87,36.45) v1(15.98,22.96) v1(16,16.38) v1(16.01,8.64) v1(16.19,14.1) v1(16.38,29.59) v1(16.51,37.72) v1(16.51,35.82) v1(16.53,32.03) v1(16.57,47.62) v1(16.84,39.75) v1(17.02,42.67) v1(17.02,41.4) v1(17.02,40.39) v1(17.14,48.96) v1(17.14,36.45) v1(17.09,35) v1(17.07,34.01) v1(17.34,45.72) v1(17.78,37.72) v1(17.79,20.45) v1(18.03,38.99) v1(18.17,43.94) v1(18.17,42.67) v1(18.17,41.4) v1(18.17,40.39) v1(18.54,30.74) v1(18.54,29.97) v1(18.54,29.21) v1(18.55,16.26) v1(18.55,13.72) v1(18.55,11.18) v1(18.55,8.64) v1(18.67,45.72) v1(18.67,39.75) v1(18.8,22.99) v1(18.92,27.94) v1(18.93,21.59) v1(19.05,38.48) v1(19.05,36.45) v1(19.05,29.59) v1(19.18,31.12) v1(19.18,30.36) v1(19.18,28.7) v1(19.43,48.96) v1(19.44,43.94) v1(19.44,42.67) v1(19.44,41.4) v1(19.44,40.39) v1(19.56,37.59) v1(19.68,30.74) v1(19.68,29.34) v1(19.68,27.94) v1(20.19,45.72) v1(20.32,30.1) v1(20.26,28.64) v1(20.71,43.94) v1(20.71,42.67) v1(20.71,41.4) v1(20.71,40.39) v1(20.95,30.74) v1(20.95,29.34) v1(20.95,28.07) v1(21.09,16.26) v1(21.09,13.72) v1(21.09,11.18) v1(21.09,8.64) v1(21.53,45.72) v1(21.46,38.86) v1(21.59,30.1) v1(21.59,28.7) v1(21.85,43.94) v1(21.85,42.67) v1(21.85,41.4) v1(21.85,40.39) v1(21.84,39.75) v1(21.97,22.99) v1(22.1,36.83) v1(22.22,30.74) v1(22.22,29.34) v1(22.22,27.94) v1(22.48,3.24) v1(22.61,37.34) v1(22.61,24.89) v1(23.25,43.94) v1(23.24,37.59) v1(23.24,5.91) v1(23.24,4.76) v1(23.24,3.24) v1(23.52,38.61) v1(23.49,35.69) v1(24,37.95) v1(24,3.43) v1(24.13,36.07) v1(24.19,12.19) v1(24.26,25.27) v1(24.43,38.61) v1(24.64,24.77) v1(24.76,39.75) v1(24.76,22.99) v1(24.94,37.95) v1(25.02,32.64) v1(25.15,48.77) v1(25.15,47.24) v1(25.27,34.93) v1(25.27,33.78) v1(25.42,26.37) v1(25.37,24.74) v1(25.72,43.62) v1(25.65,22.99) v1(25.78,32.39) v1(25.91,33.15) v1(26.04,39.24) v1(26.03,26.37) v1(26.11,24.76) v1(26.55,27.64) v1(26.54,22.99) v1(26.67,26.37) v1(26.8,33.15) v1(26.85,24.77) v1(27.08,39.22) v1(27.3,22.99) v1(27.56,39.78) v1(27.81,30.1) v1(28,43.43) v1(28.19,37.34) v1(28.19,34.93) v1(28.33,41.4) v1(28.57,35.56) v1(28.7,38.38) v1(28.7,36.42) v1(28.7,33.02) v1(28.7,29.72) v1(28.7,26.31) v1(28.7,25.5) v1(28.7,24.64) v1(31.81,25.53) v1(32.38,43.43) v1(33.15,45.34) v1(33.28,48.77) v1(33.28,46.23) v1(33.28,43.69) v1(33.34,27.62) v1(34.29,27.56) v1(34.89,29.37) v1(36.96,43.24) v1(37.21,27.56) v1(39.12,48.77) v1(39.12,46.23) v1(39.12,43.69) v1(39.24,40.77) v1(39.43,23.24) v1(39.81,43.24) v1(40.26,40.01) v1(40.58,48.77) v1(40.77,41.15) v1(41.53,40.58) v1(41.53,39.62) v1(42.1,48.77) v1(42.48,40.77) v1(42.8,40.01) v1(43.43,46.29) v1(43.43,44.2) v1(43.62,48.2) v1(44.77,16.95) v1(44.77,15.81) v1(45.72,16.95) v1(45.72,16.19) v1(45.72,15.24) v1(45.72,14.29) v1(45.73,10.16) v1(45.91,30.1) v1(45.91,29.34) v1(46.53,15.24) v1(46.67,29.34) v1(46.74,9.14) v1(46.86,16.95) v1(46.86,15.81) v1(47.08,18.67) v1(48.01,16.89) v1(48.2,18.67) v1(48.2,15.81) v1(48.96,18.1) v1(48.96,16.95) v1(49.15,44.77) v1(49.34,29.34) v1(49.34,15.81) v1(49.91,44.77) v1(50.3,32.51) v1(50.3,29.97) v1(50.29,16.95) v1(50.42,18.29) v1(50.42,15.75) v1(50.75,14.83) v1(51.44,25.34) v1(51.44,21.72) v1(51.56,1.91) v1(51.69,7.87) v1(51.69,6.1) v1(51.69,4.7) v1(51.69,3.3) v1(52.01,25.91) v1(52.2,24.57) v1(52.2,19.62) v1(52.84,32.51) v1(52.84,7.11) v1(52.83,6.1) v1(52.84,4.57) v1(52.8,3.3) v1(52.84,2.03) v1(52.96,25.34) v1(53.34,26.29) v1(53.59,8.64) v1(53.72,45.91) v1(53.85,7.24) v1(53.91,48.77) v1(53.91,47.62) v1(53.91,21.72) v1(54.1,5.71) v1(54.1,1.91) v1(54.23,4.57) v1(54.29,29.34) v1(54.29,3.43) v1(54.36,25.65) v1(54.67,22.67) v1(54.74,8.64) v1(55,7.24) v1(55.24,35.62) v1(55.38,4.57) v1(55.38,2.03) v1(55.63,25.72) v1(56.64,4.57) v1(56.64,3.3) v1(56.74,35.65) v1(56.77,1.91) v1(57.15,25.72) v1(57.41,8.26) v1(57.92,4.57) v1(57.92,2.03) v1(58.48,25.72) v1(59.05,34.1) v1(59.18,4.57) v1(59.18,3.3) v1(59.18,1.91) v1(59.63,35.24) v1(60.01,25.72) v1(60.33,5.71) v1(60.39,26.48) v1(60.46,24.89) v1(60.46,22.35) v1(60.46,19.81) v1(60.46,17.27) v1(60.46,14.73) v1(60.46,12.19) v1(60.46,8.38) v1(60.46,7.11) v1(60.46,4.57) v1(60.45,3.43) v1(60.46,2.03) v1(60.58,33.91) v1(60.58,10.41) v1(60.77,35.05) v1(61.34,20.95) v1(61.34,16) v1(61.34,9.4) v1(61.34,5.71) v1(61.47,26.16) v1(61.47,23.62) v1(61.47,18.67) v1(61.47,13.46) v1(61.47,11.3) v1(61.47,4.45) v2(31.43,18.23) v2(31.43,16.63) v2(31.43,15.83) v2(31.43,15.03) v2(31.43,14.17) v2(31.43,13.28) v2(31.55,20.13) v2(31.55,19.37) v2(32.19,18.23) v2(32.19,17.43) v2(32.19,16.63) v2(32.19,15.83) v2(32.19,15.03) v2(32.19,14.17) v2(32.19,13.28) v2(32.32,20.13) v2(32.32,19.37) v2(33.21,20.13) v2(33.21,19.37) v2(33.21,18.36) v2(33.21,17.56) v2(33.21,16.76) v2(33.21,15.96) v2(33.21,15.16) v2(33.21,14.17) v2(33.21,13.28) v2(34.01,20.13) v2(34.01,19.37) v2(34.01,18.36) v2(34.01,17.56) v2(34.01,16.76) v2(34.01,15.96) v2(34.01,15.16) v2(34.01,14.17) v2(34.01,13.28) v2(34.81,20.13) v2(34.81,19.37) v2(34.81,18.36) v2(34.81,17.56) v2(34.81,16.76) v2(34.81,15.96) v2(34.81,15.16) v2(34.81,14.17) v2(34.81,13.28) v2(35.61,20.13) v2(35.61,19.37) v2(35.61,18.36) v2(35.61,17.56) v2(35.61,16.76) v2(35.61,15.96) v2(35.61,15.16) v2(35.61,14.17) v2(35.61,13.28) v2(36.41,20.13) v2(36.41,19.37) v2(36.41,18.36) v2(36.41,17.56) v2(36.41,16.76) v2(36.41,15.96) v2(36.41,15.15) v2(36.41,14.17) v2(36.78,34.29) v2(36.78,33.54) v2(37.4,20.13) v2(37.4,19.37) v2(37.4,18.36) v2(37.4,17.56) v2(37.4,16.76) v2(37.4,15.96) v2(37.4,15.16) v2(37.4,13.4) v2(37.53,35.04) v2(37.53,34.29) v2(37.53,33.54) v2(38.16,20.13) v2(38.16,19.37) v2(38.16,13.4) v2(38.28,35.04) v2(38.28,34.29) v2(38.28,33.54) v2(38.29,18.36) v2(38.29,17.56) v2(38.29,16.76) v2(38.29,15.96) v2(38.29,15.16) v2(50.04,40.89) v2(51.44,40.89)
VBAT:
  vias: v1(44.58,33.34) v1(44.58,32.38) v1(45.34,32.38)
VBAT_CC: length 13.7
  TOP w0.14: U5.B5 20.95,33.35 20.85,33.45 20.85,33.86 v1(20.8,33.91)
  TOP w0.254: U5.B5 U5.B6
  TOP w0.508: v1(20.8,33.91) C21.1
  LYR3_PWR w0.508: v1(20.8,33.91) 20.8,36.67 22.67,38.54 22.67,39.94 J11.2
VCC_5229: length 5
  TOP w0.254: U10.11 40.15,18.01 v1(40.39,17.78) 40.5,17.67 C39.1 ; v1(40.01,10.03) 38.86,10.03 38.6,10.3 R28.1 ; U10.15 v1(40.06,20.01)
VDD_1V8_LDO: length 0.8
  TOP w0.254: U8.3 45.2,30.31 v1(44.96,30.1)
  vias: v1(46.86,32.19) v1(47.82,32.96)
VDD_2V8_LDO: length 15.6
  BOTTOM w0.762: 41.08,26.92 41.43,27.27 41.82,27.27 42.17,27.62 42.86,27.62
  BOTTOM w1.016: v1(48.01,29.91) 48.01,30.1 v1(47.05,31.05) 46.86,31.24 44.01,31.24 43.62,30.86 43.62,29.07 J30.1 42.86,27.62 ; S3.1 42.48,24.18 41.08,25.58 41.08,26.92
ALO: length 1.3
  TOP w0.203: C29.1 19.45,33.32 U5.A8
ANT: length 2.3
  TOP w0.157: R29.1 ANT1.1
AUD_CLK_1V8_CC: length 20.2
  TOP w0.127: J32.2 31.62,40.89 31.62,32 30.23,30.61 30.23,29.63 28.98,28.38 27.37,28.38 26.54,29.21 U5.B32
AUD_FSYNC_1V8_CC: length 17.8
  TOP w0.127: U5.A35 26.33,28.91 27.11,28.13 29.08,28.13 30.51,29.55 30.51,30.51 31.88,31.88 31.88,37.47 v1(32.13,37.72)
  BOTTOM w0.127: v1(32.13,37.72) 32.13,37.73 J33.2 30.49,39.31
AUD_IN_1V8_CC: length 13.6
  TOP w0.127: U5.B34 26.61,30.41 28.07,28.96 28.83,28.96 29.53,29.65 29.53,35.48 J35.2
AUDIO_NRESET_1V8_5229: length 29.1
  TOP w0.127: v1(33.53,35.05) 33.67,35.05 R39.1 34.68,34.04 U12.4 ; U10.26 34.05,21.7 v1(32.89,22.86) ; v1(33.72,31.05) 33.72,29.53 v1(34.1,29.15)
  BOTTOM w0.127: v1(33.53,35.05) 33.72,34.86 v1(33.72,31.05) ; v1(34.1,29.15) 34.1,28.57 35.24,27.43 35.81,27.43 36.77,28.38 39.05,28.38 39.16,28.49 39.34,28.49 39.59,28.24 39.59,27.51 39.97,27.12 39.97,27.06 40.01,27.03 40.01,26.1 38.38,24.48 33.62,24.48 33.15,24 33.15,23.11 v1(32.89,22.86)
BT_RF: length 3.6
  TOP w0.157: C31.1 17.94,32.08 arc(18.3,31.84) 18.72,31.75 arc(19.03,31.88) 19.15,32.19 U5.B8
BT_RF_IN: length 1
  TOP w0.157: FL1.4 15.68,34.33 C31.2
CB0: length 23.5
  TOP w0.127: U11.1 28.98,8.76 29.23,9.02 41.28,9.02 42.29,10.03 42.29,11.43 41.91,11.81 40.89,11.81 40.63,12.07 R31.2 39.38,12.57 39.25,12.69 U10.1
CB1: length 15.9
  TOP w0.127: U10.2 39.75,13.51 40.01,13.77 40.01,13.84 40.26,14.1 R32.2 40.63,13.85 40.89,13.59 42.16,13.59 42.29,13.72 43.05,13.72 43.43,13.34 43.43,10.54 41.79,8.89 41.79,8.51 U11.2
CB2: length 17.9
  TOP w0.127: U10.3 39.77,14.01 40.13,14.37 40.13,15.37 40.26,15.49 R33.2 40.63,15.11 40.75,14.99 44.06,14.99 44.58,14.48 44.58,7.1 U11.3
CBOUT: length 22.3
  TOP w0.127: U10.24 35.05,21.63 33.78,22.9 v1(33.78,23.5) ; v1(42.3,14.22) 42.17,14.1 R32.1 ; v1(42.3,16.26) 42.3,15.75 42.04,15.49 R33.1 ; v1(42.93,13.21) 42.3,12.57 R31.1
  BOTTOM w0.127: v1(42.93,13.21) 42.93,13.59 v1(42.3,14.22) v1(42.3,16.26) 40.9,16.26 39.5,17.65 39.5,19.68 35.69,23.5 v1(33.78,23.5)
CLO: length 1.2
  TOP w0.254: U5.A7 20.06,33.13 19.84,33.35 19.84,33.9 C28.1
DCLO: length 1.2
  TOP w0.203: C27.1 16.07,31.31 U5.A12
DIG_LDO_OUT: length 22.5
  TOP w0.127: U5.B15 16.05,28.61 C25.1 ; C35.1 25.88,31.61 U5.B36 ; 23.25,31.61 23.05,31.81 U5.A2
  TOP w0.254: 23.06,26.88 22.75,26.57 22.76,26.57 U5.B26 ; 23.06,26.88 23.06,27.1 22.76,27.41 ; 23.06,26.88 23.35,26.58 U5.B27 23.87,26.11 23.88,26.11 24.09,26.11 arc(24.2,26.09) 24.29,26.03 arc(24.96,25.62) C26.1 ; U5.B15 18.16,28.61 18.41,28.36 18.41,27.66 18.67,27.41 22.76,27.41 ; 22.76,27.41 22.96,27.61 22.96,30.53 23.44,31.01 U5.B35 U5.B36 23.25,31.61 ; U5.A3 U5.A2
DVIO_1V8_5229: length 4.1
  TOP w0.254: R12.1 31.88,10.67 v1(31.37,11.18) ; v1(29.21,14.86) 29.21,15.11 C37.1 29.34,16.01 29.34,16.64 29.72,17.01 U10.40
HCI_CTS_1V8_CC: length 26.3
  TOP w0.127: U10.23 35.55,21.72 35.25,22.03 35.25,22.03 v1(34.29,22.99) ; v1(21.59,19.18) 21.72,19.3 R35.2
  BOTTOM w0.127: v1(21.59,19.18) 21.78,18.99 22.92,18.99 23.43,18.48 23.43,14.69 24.64,13.49 26.37,13.49 26.91,14.03 26.91,14.43 29.05,16.57 29.05,18.78 29.91,19.64 29.91,20.38 31.47,21.95 33.25,21.95 v1(34.29,22.99)
HCI_RTS_1V8_CC: length 33.9
  TOP w0.127: v1(22.1,16.76) 22.14,16.8 22.14,19.47 22.59,19.93 R34.2 ; U10.22 36.05,21.58 35.5,22.13 35.36,22.28 35.36,22.68 v1(35.05,22.99)
  BOTTOM w0.127: v1(22.1,16.76) 22.29,16.57 22.29,13.34 25.53,10.1 29.15,10.1 30.35,11.3 30.35,20.45 31.43,21.53 33.59,21.53 v1(35.05,22.99)
HCI_RX_1V8_CC: length 21.3
  TOP w0.127: U10.37 29.68,18.51 v1(29.53,18.67) ; R27.2 20.71,19.11 20.75,19.06 v1(20.75,19.05)
  BOTTOM w0.127: v1(29.53,18.67) 29.89,18.31 29.89,13.14 29.51,12.76 27.43,12.76 27.22,12.98 24.17,12.98 22.67,14.48 22.67,17.72 21.65,18.73 21.02,18.73 20.76,19.05 v1(20.75,19.05)
HCI_TX_1V8_CC: length 16.7
  TOP w0.127: R26.2 23.5,19.3 v1(22.67,18.48) ; U10.38 29.49,18.01 v1(29.47,18.03)
  BOTTOM w0.127: v1(29.47,18.03) 29.47,16.63 27.18,14.35 27.18,13.94 26.47,13.23 24.49,13.23 23.05,14.67 23.05,18.1 v1(22.67,18.48)
I2C_SCL_1V8_5229: length 3.4
  TOP w0.127: U10.35 30.05,19.51 29.62,19.09 29.35,19.09 29.11,18.84 29.11,18.36 J34.2
I2C_SDA_1V8_5229: length 2.4
  TOP w0.127: J36.1 28.02,20.01 U10.34
IOVDD_1V8_MIC: length 11.5
  TOP w0.127: 41.86,36.02 R17.1
  TOP w0.508: R16.1 41.86,36.02 ; v1(35.62,37.15) 35.85,37.38 36.35,37.38 v1(36.39,37.34) ; v1(36.39,37.34) 37.34,37.34 ; v1(36.39,37.34) C54.1 ; 37.34,37.34 38.29,37.34 ; 37.34,37.34 C53.1 ; R17.1 41.9,36.21 40.77,37.34 v1(39.43,37.34) ; v1(39.43,37.34) C56.1 ; v1(39.43,37.34) 38.29,37.34 ; 38.29,37.34 C55.1
  vias: v1(35.62,38.1)
JTAG_PWR_3V3: length 13.3
  BOTTOM w1.016: S3.3 48.99,22.99 53.09,22.99 54.1,24 57.78,24 58.68,23.11 J2.2
LED1: length 1.3
  TOP w0.127: U10.19 37.55,22.3 R6.1
LED2: length 1.3
  TOP w0.127: R7.1 37.05,22.25 U10.20
LED3: length 1.5
  TOP w0.127: R15.1 36.55,21.86 U10.21
MLDO_OUT: length 11.9
  TOP w0.127: U5.A5 21.25,31.68
  TOP w0.203: C20.1 21.49,33.67 21.25,33.44 U5.A5 ; 21.25,31.68 21.62,31.32 22.35,31.32 22.61,31.57 22.61,31.57 22.76,31.72 U5.B2
  TOP w0.254: U5.A9 18.85,33.34 18.69,33.51 17.91,33.51 17.89,33.49 v1(17.78,33.49) ; U5.B7 19.76,32.31 v1(19.76,31.73)
  TOP w0.305: 21.25,31.68 21.21,31.73 v1(19.76,31.73)
  LYR3_PWR w0.381: v1(17.78,33.49) 19.34,33.49 19.76,33.08 v1(19.76,31.73)
NRST/SBWTDIO_5229: length 20.4
  TOP w0.127: v1(40.89,10.03) 40.63,10.3 C43.1 R28.2 39.62,11.06 39.62,11.56 39.5,11.68 38.73,11.68 38.55,11.87 U10.64
  BOTTOM w0.127: v1(40.89,10.03) 41.28,9.65 41.28,9.65 42.42,8.51 52.2,8.51 52.83,9.14 J2.11
NSHUTDOWN_1V8_CC: length 38.8
  TOP w0.127: U10.25 34.55,21.77 33.36,22.96 33.36,23.24 32.77,23.84 32.77,29.44 32.38,29.82 v1(32.38,33.91) ; U5.A6 20.65,33.33 20.25,33.73 20.25,37.9 20.64,38.29 22.17,38.29 23.37,39.5 23.37,40.13 23.75,40.51 28.83,40.51 29.22,40.13 29.22,34.67 v1(28.96,34.41)
  BOTTOM w0.127: v1(32.38,33.91) 32.38,34.1 32.07,34.41 v1(28.96,34.41)
RF_ANT: length 2.3
  TOP w0.157: FL1.2 R29.2
SLO: length 2.4
  TOP w0.203: 23.67,32.31 U5.B1
  TOP w0.305: C30.1 24.48,33.12 23.67,32.31
SLOW_CLK_1V8_CC: length 34.5
  TOP w0.127: v1(19.62,19.24) 19.82,19.44 R25.2 ; R10.2 R11.1 39.24,26.67 39.12,26.8 39.12,26.78 39.1,26.78 39.1,26.77 39.14,26.77 39.14,26.76 v1(39.12,26.76)
  BOTTOM w0.127: v1(39.12,26.76) 39.14,26.76 39.14,26.77 39.1,26.77 39.1,26.78 38.29,25.97 31.43,25.97 30.37,24.91 30.37,22.46 29.4,21.48 27.58,21.48 27.08,20.98 27.08,19.25 26.99,19.17 26.99,18.49 26.89,18.39 26.89,16.27 26.86,16.24 26.86,16.19 26.53,15.86 24.53,15.86 24.12,16.27 24.12,19.21 23.31,20.02 20.35,20.02 19.74,19.4 19.74,19.35 v1(19.62,19.24)
SMCLK_5229: length 2.6
  TOP w0.127: J17.1 33.05,21.94 U10.28
TCK_5229: length 21
  TOP w0.127: v1(37.85,11.43) 38.05,11.63 U10.63
  BOTTOM w0.127: v1(37.85,11.43) 37.89,11.39 41.45,11.39 42.17,10.67 52.08,10.67 55.63,14.22 J2.7
TDI_5229: length 27.4
  TOP w0.127: v1(36.84,10.67) 36.71,10.79 36.71,11.18 37.05,11.52 U10.61
  BOTTOM w0.127: v1(36.84,10.67) 36.71,10.79 36.71,11.81 37.59,12.7 41.92,12.7 42.68,11.94 50.81,11.94 52.33,13.46 52.33,15.49 J2.3
TDO_5229: length 31.2
  TOP w0.127: U10.60 36.55,11.4 36.07,10.92 v1(36.07,10.67)
  BOTTOM w0.127: v1(36.07,10.67) 36.2,10.79 36.2,13.08 37.22,14.1 41.45,14.1 42.97,12.57 50.3,12.57 51.44,13.72 51.44,17.14 J2.1
TEST/SBWTCK_5229: length 29
  TOP w0.127: v1(35.31,11.43) 35.69,11.43 36.05,11.79 U10.59
  BOTTOM w0.127: v1(35.31,11.43) 35.05,11.17 35.05,10.54 35.81,9.78 38.73,9.78 39.62,10.67 41.15,10.67 42.16,9.65 52.08,9.65 55.25,12.83 57.28,12.83 J2.8
TMS_5229: length 24.9
  TOP w0.127: v1(37.85,10.67) 37.34,11.18 37.34,11.51 37.55,11.72 U10.62
  BOTTOM w0.127: v1(37.85,10.67) 37.85,10.84 37.43,11.26 37.43,11.65 37.78,12 41.73,12 42.42,11.3 51.31,11.3 53.09,13.08 53.09,13.72 J2.5
UBAL5: length 9.7
  TOP w0.157: R30.1 P3.1
VCORE: length 1.4
  TOP w0.254: C41.1 38.55,22.41 U10.17
VIO_1V8_CC: length 17.4
  TOP w0.127: v1(23.49,28.32) 23.5,28.31 U5.A34 ; U5.A38 23.75,30.71 23.49,30.46 23.49,30.05
  TOP w0.254: 20.1,26.81 19.76,26.47 U5.B21 ; 20.1,26.81 18.54,26.81 ; 20.1,26.81 20.35,26.56 ; U5.B25 v1(22.15,26.86) 20.66,26.86 20.35,26.56 ; 20.35,26.56 U5.B22 ; 18.54,26.81 18.55,26.8 U5.B19 ; 18.54,26.81 U5.B18 17.85,26.81 17.85,26.32 17.42,25.89 16.51,25.89 v1(16.23,26.16) 16.01,26.38 C17.1 16.01,27.53 v1(16.34,27.86) 16.79,28.31 17.15,28.31 U5.A17 ; 23.49,30.05 v1(23.49,28.32)
N81643: length 25.8
  TOP w0.127: v1(25.28,21.72) 26.67,21.72 26.83,21.88 31.34,21.88 31.55,21.67 U10.31
  BOTTOM w0.127: 18.03,8.53 18.03,19.2 19.76,20.93 24.49,20.93 v1(25.28,21.72)
N81789: length 28.9
  TOP w0.127: v1(26.17,22.14) 26.26,22.23 31.63,22.23 32.05,21.8 U10.30
  BOTTOM w0.127: 21.62,7.15 21.62,14.96 18.67,17.91 18.67,19.47 19.87,20.68 24.7,20.68 25.17,21.15 25.34,21.15 26.17,21.98 v1(26.17,22.14)
N134906: length 28.9
  TOP w0.127: v1(39.62,36.39) 39.66,36.39 39.99,36.06 ; 39.99,36.06 U12.18 ; 39.99,36.06 R17.2
  BOTTOM w0.127: J36.2 25.46,20.7 27.16,22.4 28.87,22.4 29.34,22.86 29.34,28.19 29.97,28.83 32.64,28.83 35.62,31.81 35.62,35.81 36.2,36.39 v1(39.62,36.39)
N140210: length 20.5
  TOP w0.508: J39.5 65.91,26.57 J37.1
N140367: length 1.2
  TOP w0.254: C60.1 R37.1
N148311: length 7.5
  TOP w0.127: J32.1 34.67,40.39 34.67,35.98 35.12,35.54 U12.1
N148461: length 3.2
  TOP w0.127: J35.1 35.05,34.48 35.52,34.48 U12.3
N148590: length 5.4
  TOP w0.127: U12.2 35.06,35.04 34.29,35.81 34.29,38.11 J33.1
N151083: length 1.7
  TOP w0.254: U12.11 38.37,32.24 38.37,31.87 38.61,31.64 38.7,31.64 38.86,31.47 C60.2
N151287: length 95.7
  TOP w0.508: J39.4 66.87,36.33 v1(66.87,30.48)
  BOTTOM w0.508: J28.1 13.34,8.19 19.43,2.1 23.49,2.1 23.82,1.77 26.01,1.77 26.91,2.67 68.45,2.67 68.58,2.79 68.58,30.35 68.45,30.48 v1(66.87,30.48)
N151328: length 1.4
  TOP w0.254: U12.5 34.63,33.54 R19.2
N151337: length 1.5
  TOP w0.254: U12.8 36.78,31.97 C61.2
N153645: length 31.6
  TOP w0.127: U12.17 40.01,35.04 ; 40.01,35.04 40.39,35.42 v1(40.39,35.43) ; 40.01,35.04 40.18,34.86 R16.2
  BOTTOM w0.127: v1(40.39,35.43) 40.01,35.81 36.39,35.81 36.2,35.62 36.2,32 32.77,28.57 30.25,28.57 29.59,27.91 29.59,22.73 29,22.14 27.27,22.14 26.29,21.17 26.29,20.49 26.39,20.39 26.39,19.62 26.29,19.52 26.29,19.24 25.55,18.5 J34.1
N160490: length 14.1
  TOP w0.127: 64.77,43.62 53.72,43.62 53.34,44.01 51.57,44.01 R13.1
N163005: length 1.4
  TOP w0.254: R20.1 40.73,33.54 U12.14
N180634: length 43.7
  TOP w0.254: R19.1 33.15,33.1 33.15,29.15 34.1,28.19 v1(35.43,28.19) 35.76,27.86 R36.2 ; 63.28,36.96 60.01,36.96 47.82,24.77 42.26,24.77 40.2,26.83 v1(40.2,28.77)
  BOTTOM w0.254: v1(40.2,28.77) 39.51,28.77 39.47,28.81 39.03,28.81 38.98,28.77 36,28.77 v1(35.43,28.19)
N180654: length 1.1
  TOP w0.254: C61.1 R36.1
N180794: length 34.6
  TOP w0.254: R20.2 41.85,30.86 40.36,29.38 39.83,29.38 39.59,29.13 39.59,28.21 R37.2 39.28,27.67 39.62,27.33 39.62,26.86 42.29,24.19 48.58,24.19 51.54,27.16 J39.3
N200636: length 1.1
  TOP w0.127: R3.1 49.85,39.36 49.99,39.5 U9.2
N200654: length 4
  TOP w0.127: D1.2 50.56,45.52 50.56,42.48 50.49,42.41 U9.10
N200660: length 2
  TOP w0.127: D1.1 48.2,45.21 R4.2
N200680: length 1.2
  TOP w0.127: R5.1 51.25,39.24 50.99,39.5 U9.4
N200686: length 8.3
  TOP w0.152: U9.9 v1(50.99,42.61)
  BOTTOM w0.152: J14.2 48.01,38.98 48.01,40.77 48.96,41.72 50.1,41.72 v1(50.99,42.61)
N200706: length 1.6
  TOP w0.127: R14.2 52.14,39.24 52.01,39.37 51.62,39.37 51.49,39.5 U9.5
N200710: length 1.8
  TOP w0.127: U9.8 51.49,43.05 R13.2
N200714: length 3.9
  TOP w0.127: U9.6 52.33,39.94 52.77,40.39 52.77,42.8 D4.2
N200730: length 1.1
  TOP w0.127: R8.1 49.99,42.8 U9.11
N200762: length 18.2
  TOP w0.127: R14.1 v1(52.14,37.22) ; v1(61.15,44.35) J4.3
  BOTTOM w0.127: v1(61.15,44.35) 55.97,44.35 52.14,40.52 v1(52.14,37.22)
N200794: length 5.1
  BOTTOM w1.016: J16.2 45.22,38.86 S2.1
N201837: length 12.1
  TOP w0.127: U5.A32 25.34,27.11 25.52,26.94 27.04,26.94 27.43,26.54 27.43,24.64 27.05,24.26 24.23,24.26 23.5,23.52 23.5,22.31 23.5,21.86 R34.1
N201839: length 5.3
  TOP w0.127: U5.A29 23.05,25.08 23.25,24.89 23.25,22.21 22.51,21.47 22.22,21.47 R35.1
N201841: length 12.5
  TOP w0.127: U5.A33 25.25,27.71 25.77,27.19 27.29,27.19 27.69,26.8 27.69,24.51 27.14,23.96 24.3,23.96 23.75,23.42 23.75,21.23 R26.1
N201843: length 6.1
  TOP w0.127: U5.A26 21.25,25.04 22.48,23.81 22.48,22.49 21.97,21.98 21.34,21.98 20.7,21.34 20.7,20.97 R27.1
N202027: length 9.5
  TOP w0.127: C22.2 25.87,38.43 Y1.1 25.47,36.88 22.83,36.88 22.3,36.35 22.3,34.01 21.55,33.27 U5.B4
N202029: length 9.3
  TOP w0.127: C23.2 26.92,34.84 Y1.3 26.92,35.97 26.31,36.58 23.11,36.58 22.66,36.12 22.66,33.91 21.85,33.11 U5.A4
N202071: length 5.9
  TOP w0.127: U5.A25 20.65,25.14 21.34,24.46 v1(21.34,24.13) ; v1(19.62,22.01) 19.82,21.81 R25.1
  BOTTOM w0.127: v1(19.62,22.01) 20.29,22.01 20.83,22.54 20.83,23.62 v1(21.34,24.13)
N202119: length 9.9
  TOP w0.127: J18.1 21.17,17.82 21.17,21.21 21.69,21.72 22.36,21.72 22.73,22.1 22.73,23.98 21.55,25.16 U5.B24
N203803: length 4.8
  TOP w0.127: U10.13 39.84,19.01 40.51,19.68 40.51,20.19 40.64,20.32 41.06,20.32 C46.2 41.39,20.31 41.78,20.7 42.56,20.7 Y2.2
N203825: length 4.2
  TOP w0.127: Y2.1 42.56,18.92 41.78,18.92 41.52,19.19 C47.2 40.55,19.19 39.88,18.51 U10.12
N203855: length 4.1
  TOP w0.127: J15.1 29.46,12.45 29.46,13.72 29.76,14.01 U10.46
N203891: length 17.8
  TOP w0.127: U10.56 34.55,11.69 34.03,11.16 C44.1 ; R12.2 C44.1 ; C44.1 34.03,9.9 33.78,9.65 20.02,9.65 S1.2
N203905: length 1.6
  TOP w0.127: D2.1 37.72,24.32 R6.2
N203911: length 1.9
  TOP w0.127: D3.1 36.45,24.07 36.45,23.89 R7.2
N203925: length 3.9
  TOP w0.127: U10.18 38.05,21.84 38.22,22.01 38.22,22.18 38.21,22.19 38.21,24.87 R10.1
N203941: length 20.5
  TOP w0.508: 50.16,20.25 49.88,19.96 49.88,19.96 50.06,19.24 50.19,19.12 50.87,19.12 51.95,18.03 57.41,18.03 J2.4 57.41,20.57 54.86,20.57 54.61,20.83 50.23,20.83 J6.2 50.16,20.25
N203951: length 2.5
  TOP w0.127: J15.2 28.79,13.72 29.59,14.51 U10.45
N203983: length 30
  TOP w0.127: v1(24.26,21.97) 24.94,21.3 26.86,21.3 26.96,21.4 30.29,21.4 30.48,21.21 U10.32
  BOTTOM w0.127: 10.17,18.71 15.24,13.64 17.53,13.64 17.78,13.89 17.78,19.09 17.78,19.3 19.66,21.18 23.47,21.18 v1(24.26,21.97)
N203997: length 2.5
  TOP w0.127: D5.1 35.49,23.51 R15.2
N205896: length 23.1
  TOP w0.127: v1(29.95,35.04) 29.97,35.01 29.97,29.74 28.93,28.7 27.81,28.7 26.7,29.81 U5.B33
  BOTTOM w0.127: v1(29.95,35.04) 29.97,35.06 29.97,35.71 29.59,36.09 29.59,36.13 29.34,36.39 29.34,41.72 28.77,42.29 J23.1
N1641850: length 2.7
  TOP w0.127: TP8.1 34.67,31.05 35.96,32.34 U12.7
N1644250: length 2
  TOP w0.127: U12.6 34.92,32.38 TP11.1
N1647250: length 5.8
  TOP w0.127: U12.24 35.39,36.24 35.05,36.58 35.05,39.62 TP7.1
N2008820: length 1.4
  TOP w0.127: 52.39,44.83 52.39,45.39 52.72,45.72 R9.2

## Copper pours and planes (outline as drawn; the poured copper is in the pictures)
AVDD_MIC on TOP: 36.77,31.62 36.77,30.1 38.48,30.1 38.48,31.62 38.1,31.62 38.1,32.58 37.72,32.96 37.53,32.77 37.53,31.62
GND on TOP (solid shape): 12.66,29.46 11.66,29.46 11.66,33.26 12.66,33.26
GND on TOP (solid shape): 22.21,39.01 18.41,39.01 18.41,40.01 22.21,40.01
GND on TOP (solid shape): 22.21,22.71 18.41,22.71 18.41,23.71 22.21,23.71
GND on TOP (solid shape): 28.96,29.46 27.96,29.46 27.96,33.26 28.96,33.26
GND on TOP (solid shape): 12.66,23.71 16.21,23.71 16.21,22.71 11.66,22.71 11.66,27.26 12.66,27.26
GND on TOP (solid shape): 16.21,39.01 12.66,39.01 12.66,35.46 11.66,35.46 11.66,40.01 16.21,40.01
GND on TOP (solid shape): 28.96,35.46 27.96,35.46 27.96,39.01 24.41,39.01 24.41,40.01 28.96,40.01
GND on TOP (solid shape): 28.96,22.71 24.41,22.71 24.41,23.71 27.96,23.71 27.96,27.26 28.96,27.26
GND on TOP (solid shape): 1.91,32.58 3.91,32.58 3.91,33.58 4.91,33.58 4.91,30.58 3.91,30.58 3.91,31.58 2.91,31.58 2.91,25.58 5.77,25.58 5.77,33.58 7.91,33.58 7.91,32.58 6.91,32.58 6.91,31.58 7.91,31.58 7.91,30.43 6.84,30.43 6.84,23.6 0.91,23.6 0.91,49.58 1.91,49.58
GND on TOP: 26.54,32.51 26.54,31.24 27.56,31.24 27.56,32.51
GND on TOP: 7.75,29.34 7.75,29.34 7.75,49.4 46.74,49.4 46.8,49.47 47.24,49.02 53.47,49.02 53.47,49.02 71.63,49.02 71.63,47.82 71.25,47.82 71.25,41.15 71.63,41.15 71.63,1.52 62.11,1.52 61.98,1.4 7.77,1.4 7.75,1.42 ; 37 cut-outs
GND on BOTTOM: 7.88,49.53 7.88,1.65 8.13,1.4 71.63,1.4 71.63,49.53 ; 5 cut-outs
GND on LYR2_GND: 7.88,49.53 7.88,1.65 8.13,1.4 61.82,1.4 61.95,1.52 71.82,1.52 71.82,49.53
GND on LYR3_PWR: outline of 118 points within 7.88,1.4 71.63,49.53 ; 1 cut-out
VBAT on TOP: 44.39,31.05 45.72,31.05 45.72,33.34 44.96,34.1 44.96,36 44.77,36.2 43.24,36.2 42.86,35.81 42.86,31.24 43.24,30.86 44.2,30.86
VBAT on LYR3_PWR: 39.81,39.62 39.81,32 44.58,32 44.96,32.38 44.96,36 44.77,36.2 42.1,36.2 41.91,36.39 41.91,40.01 43.05,41.15 43.05,43.24 42.83,43.47 42.52,43.47 41.98,44.01 25.53,44.01 25.34,43.81 25.34,40.96 25.53,40.77 28.77,40.77 28.96,40.96 28.96,41.53 29.15,41.72 34.29,41.72 34.48,41.53 34.48,39.81 34.67,39.62
VCC_5229 on LYR3_PWR: 43.95,19.05 40.77,19.05 40.39,19.43 40.39,20.32 40.26,20.45 39.24,20.45 39.12,20.32 39.12,9.91 39.25,9.78 40.26,9.78 40.39,9.91 40.39,10.29 40.14,10.54 40.14,17.14 40.65,17.65 47.25,17.65 47.5,17.91 47.5,21.21 46.67,22.04 46.67,25.34 46.48,25.53 44.39,25.53 44.2,25.34 44.2,24.19 44.83,23.56 44.83,22.61 44.84,22.61 44.84,19.94
VDD_1V8_LDO on TOP: 48.2,33.34 47.43,33.34 47.24,33.15 47.24,32.58 46.48,32.58 45.91,32 45.91,31.62 48.01,31.62 48.39,32 48.39,33.15
VDD_1V8_LDO on LYR3_PWR: 32.58,23.81 32.95,24.19 38.48,24.19 43.81,29.53 45.34,29.53 45.34,30.48 45.72,30.86 46.67,30.86 47.43,31.62 47.43,32 48.2,32 48.2,33.72 45.34,33.72 45.15,33.53 45.15,32.19 44.77,31.81 39.81,31.81 36.39,28.38 29.53,28.38 29.34,28.19 29.34,22.85 28.96,22.48 24,22.48 22.86,21.34 19.43,21.34 19.24,21.15 18.48,21.15 18.29,20.95 18.29,20.19 17.34,19.24 14.86,19.24 14.67,19.05 14.67,14.48 15.62,13.53 18.86,13.53 19.05,13.34 19.05,13.14 19.24,12.95 26.29,12.95 26.48,13.14 26.48,15.62 26.86,16 28.96,16 30.1,17.14 30.48,17.14 30.67,17.34 30.67,20.38 31.05,20.76 32.38,20.76 32.58,20.95
VDD_2V8_LDO on TOP: 48.01,31.43 45.91,31.43 45.91,31.05 46.67,31.05 47.05,30.67 47.24,30.67 47.24,29.72 47.62,29.34 48.01,29.34 48.2,29.53 48.2,31.24
ANT on TOP (solid shape): 8.02,34.26 5.69,34.26 4.84,33.31 4.73,33.43 5.62,34.41 8.02,34.41
DVIO_1V8_5229 on LYR3_PWR: 29.15,15.81 27.05,15.81 26.67,15.43 26.67,12.95 26.48,12.76 19.24,12.76 19.05,12.57 19.05,4.57 19.81,3.81 23.62,3.81 24.19,4.38 24.19,8.31 24.64,8.76 33.66,8.76 33.91,9.02 33.91,12.19 33.91,12.19 33.91,12.38 33.72,12.57 31.05,12.57 30.67,12.95 30.67,16.76 30.48,16.95 30.29,16.95
IOVDD_1V8_MIC on TOP: 36.96,35.81 36.96,36.84 36.88,36.77 35.43,36.77 35.43,38.48 40.01,38.48 40.01,37.15 39.62,36.77 38.18,36.77 38.1,36.84 38.1,35.81
IOVDD_1V8_MIC on LYR3_PWR: 39.62,32 39.62,35.43 39.81,35.43 39.81,37.53 39.62,37.53 39.62,39.43 39.43,39.62 35.43,39.62 35.05,39.24 35.05,31.43 30.1,31.43 29.34,30.67 29.34,28.77 29.53,28.57 36.2,28.58
USB_5V on TOP: 44.96,33.91 44.77,34.1 44.77,36 44.96,36.2 46.48,36.2 47.05,36.77 47.05,40.01 47.24,40.2 49.53,40.2 49.72,40.01 49.72,39.62 49.34,39.24 49.34,38.67 49.15,38.48 48.58,38.48 48.39,38.29 48.39,36.58 48.77,36.2 52.39,36.2 53.09,36.9 53.09,38.73 53.09,38.73 53.09,41.4 54.36,42.67 54.36,43.05 54.1,43.31 54.1,44.77 63.44,44.77 63.63,44.58 63.63,43.05 66.29,43.05 66.29,42.1 56.96,42.1 56.65,41.78 55.25,41.78 54.23,40.77 54.23,35.57 52.58,33.91 ; 2 cut-outs
VIO_1V8_CC on LYR3_PWR: 17.14,19.43 18.1,20.38 18.1,21.15 17.91,21.34 15.81,21.34 15.62,21.53 15.62,25.34 16,25.72 22.29,25.72 24.38,27.81 24.38,29.34 24,29.72 23.24,29.72 22.99,29.47 22.99,28.13 22.29,27.43 17.66,27.43 17.27,27.82 16.64,28.58 15.43,28.58 15.43,28.58 15.05,28.58 12.76,26.29 12.76,20.95 14.29,19.43
N200648 on TOP: 49.34,43.24 48.2,43.24 47.82,43.62 47.82,46.29 48.01,46.48 50.86,46.48 51.24,46.1 51.24,45.91 51.44,45.72 51.82,45.72 52.01,45.91 52.01,47.05 51.82,47.24 50.29,47.24 50.1,47.43 50.1,48.58 49.72,48.96 47.24,48.96 46.48,48.2 46.48,42.1 47.05,41.53 49.53,41.53 49.72,41.72 49.72,42.1 49.53,42.29 49.53,43.05
N200702 on LYR3_PWR: 52.2,49.53 52.39,49.34 52.39,46.67 52.2,46.48 47.24,46.48 47.06,46.29 47.06,46.29 46.68,45.91 46.68,43.82 46.48,43.62 42.67,43.62 42.1,44.2 25.53,44.2 25.34,44.39 25.34,45.72 25.15,45.91 22.48,45.91 21.91,46.48 21.91,49.15 21.91,49.15 22.1,49.34 22.1,49.4 22.23,49.53

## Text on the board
BOTTOM: 6576620 | L 4
Ref Des/Assembly Bottom: VIEWED FROM TOP SIDE | ASSEMBLY - BOTTOM SIDE | 2
Board Geometry/Soldermask Bottom: SOLDERMASK - SECONDARY SIDE | 9
Package Geometry/Pastemask Bottom: SOLDERPASTE - SECONDARY SIDE | 8
Ref Des/Silkscreen Bottom: BT-MSP-AUDSOURCE | REV 1.1 | SILKSCREEN - SECONDARY SIDE | 6
User.Comments: TI-ECS | 12 | BT-MSP-AUDSOURCE | 6576620 | TEXAS INSTRUMENTS | 1.1 | 03/07/14
TOP: L 1
Ref Des/Assembly Top: VIEWED FROM TOP SIDE
Board Geometry/Soldermask Top: SOLDERMASK - PRIMARY SIDE | 8
Package Geometry/Pastemask Top: SOLDERPASTE - PRIMARY SIDE | 7
Ref Des/Silkscreen Top: C | Previous | A | LI | Pause/Play | ISET2 | Next | D | CHG | GND | 1 RX | LDO/JTAG | TEXAS | INSTRUMENTS | RST | B | OFF | ON | SILKSCREEN - PRIMARY SIDE | 5
LYR2_GND: L 2
LYR3_PWR: L 3
DIMENSION: SHIELD DIMENSIONS | 1 | 12 | FABRICATION DRAWING
L1: LAYER 1 - PRIMARY SIDE | 1
User.5: LAYER 2 - GND | 2
User.6: LAYER 3 - GND/PWR | 3
User.7: LAYER 4 - BOTTOM SIDE | 4
User.8: OUTLINE | 11 | 12
User.9: ASSEMBLY TOP | 12
User.10: FAB DRAWING | 10 | 12
User.14: 15. | 16. | 17.  VIAS TO BE TENTED ON BOTH SIDES. | 6.2 MIL TRACES ON TOP SIDE (LAYER 1) ARE TO BE 50 OHM +/-10% | THESE WILL DECOUPLE TO THE GND PLANE ON LAYER 2. | ALL VIAS WILL BE FILLED WITH NON-CONDUCTIVE EPOXY. | X | VIEWED FROM TOP SIDE
User.15: SCALE: NONE | LAYER 1 | LAYER 3 | LAYER 2 | LAYER 4 | BSLK | SMS | TSLK | SMC | LAYER SCHEDULE
User.17: ALL DIMENSION ARE IN MILS | UNLESS OTHERWISE SPECIFIED | PRASHANTHA | ZAHID HAQ | MIIUEL SANCHEZ | SCALE  NONE | REV | 1.1 | SIZE | B | SHEET   OF | 1 | DRAWN BY: | CHECKED BY: | APPROVED BY: | ASSEMBLY TOP SIDE | ASSEMBLY: | BT-MSP-AUDSOURCE | TEXAS INSTRUMENTS
User.19: FIGURE | SIZE | 8.0 | 12.0 | 26.0 | 27.5591 | 33.622 | 35.4 | 38.0 | 39.3701 | 62.9921 | DRILL CHART: TOP to BOTTOM | ALL UNITS ARE IN MILS | TOLERANCE | +0.0/-8.0 | +0.0/-12.0 | +0.0/-0.0 | +3.0/-3.0 | +2.0/-2.0 | +2.3622/-2.3622 | PLATED | NON-PLATED | QTY | 455 | 90 | 4 | 2 | 3 | 26 | 36
